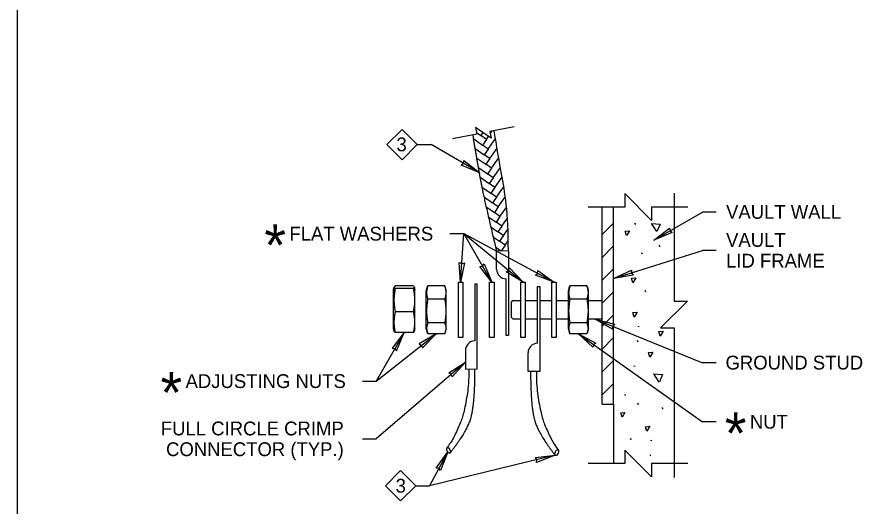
# Model space of a CAD drawing. Extents: x 99862 to 103151, y 100000 to 105076.
# Drawn here: x 99862 to 100847, y 103941 to 104508 of the extents above; entities that cross this region are included whole.
import ezdxf

# ---------------------------------------------------------------- set-up
doc = ezdxf.new("R2010")
doc.units = 0
for name, color, linetype in [('Level 1', 7, 'Continuous'), ('Level 10', 7, 'Continuous'), ('Level 11', 7, 'Continuous'), ('Level 13', 7, 'Continuous'), ('Level 15', 7, 'Continuous'), ('Level 20', 7, 'Continuous'), ('Level 30', 7, 'Continuous'), ('Level 8', 7, 'Continuous')]:
    doc.layers.add(name, color=color, linetype=linetype)

msp = doc.modelspace()

# ---------------------------------------------------------------- linework, layer by layer
at = {"layer": 'Level 1'}
for p, q in [((100539.11, 104060.59), (100539.11, 104288.59)), ((100552.29, 104060.59), (100552.29, 104288.59)), ((100552.29, 104270.05), (100539.11, 104256.87)), ((100552.29, 104243.53), (100539.11, 104230.35)), ((100552.29, 104217.01), (100539.11, 104203.84)), ((100552.29, 104190.5), (100539.11, 104177.32)), ((100552.29, 104163.98), (100539.11, 104150.8)), ((100552.29, 104137.47), (100539.11, 104124.29)), ((100552.29, 104110.95), (100539.11, 104097.77)), ((100552.29, 104084.43), (100539.11, 104071.25)), ((100539.11, 104060.59), (100552.29, 104060.59)), ((100552.29, 104060.59), (100552.29, 103991.68))]:
    msp.add_line(p, q, dxfattribs=at)
msp.add_lwpolyline([(99862, 102999.5), (103151, 102999.5), (103151, 105075.5), (99862, 105075.5)], close=True, dxfattribs=at)
at = {"layer": 'Level 10'}
for p, q in [((100297.82, 104193.2), (100298.6, 104196.01)), ((100299.66, 104197.24), (100298.6, 104196.01)), ((100320.67, 104197.24), (100299.66, 104197.24)), ((100320.67, 104197.24), (100321.73, 104196.01)), ((100321.73, 104196.01), (100322.52, 104193.19)), ((100335.58, 104191.07), (100337.09, 104196.48)), ((100337.09, 104196.46), (100337.31, 104197.24)), ((100357.01, 104197.24), (100337.31, 104197.24)), ((100357.24, 104196.46), (100357.01, 104197.24)), ((100357.23, 104196.48), (100358.74, 104191.07)), ((100500.06, 104191.07), (100501.56, 104196.48)), ((100501.56, 104196.46), (100501.79, 104197.24)), ((100521.48, 104197.24), (100501.79, 104197.24)), ((100521.71, 104196.46), (100521.48, 104197.24)), ((100521.7, 104196.48), (100523.21, 104191.07)), ((100320.67, 104194.25), (100299.66, 104194.25)), ((100335.58, 104148.22), (100335.58, 104191.07)), ((100358.74, 104148.22), (100358.74, 104191.07)), ((100500.06, 104148.22), (100500.06, 104191.07)), ((100523.21, 104148.22), (100523.21, 104191.07)), ((100357.01, 104182.09), (100337.31, 104182.09)), ((100436.13, 104180.58), (100433.88, 104178.33)), ((100433.88, 104178.33), (100433.88, 104160.96)), ((100436.13, 104180.58), (100444.98, 104180.58)), ((100450.25, 104180.58), (100464.39, 104180.58)), ((100467.03, 104180.58), (100480.84, 104180.58)), ((100486.11, 104180.58), (100500.06, 104180.58)), ((100521.48, 104182.09), (100501.79, 104182.09)), ((100523.21, 104180.58), (100539.11, 104180.58)), ((100320.67, 104167.35), (100299.66, 104167.35)), ((100433.88, 104160.96), (100436.13, 104158.71)), ((100444.98, 104158.71), (100436.13, 104158.71)), ((100464.39, 104158.71), (100450.25, 104158.71)), ((100480.84, 104158.71), (100467.03, 104158.71)), ((100500.06, 104158.71), (100486.11, 104158.71)), ((100539.11, 104158.71), (100523.21, 104158.71)), ((100298.6, 104144.68), (100297.82, 104147.49)), ((100322.51, 104147.49), (100321.73, 104144.68)), ((100337.3, 104142.05), (100335.58, 104148.22)), ((100357.01, 104154.5), (100337.31, 104154.5)), ((100358.74, 104148.22), (100357.23, 104142.81)), ((100501.78, 104142.05), (100500.06, 104148.22)), ((100521.48, 104154.5), (100501.79, 104154.5)), ((100523.21, 104148.22), (100521.7, 104142.81)), ((100299.66, 104143.45), (100298.6, 104144.68)), ((100320.67, 104143.45), (100299.66, 104143.45)), ((100320.67, 104143.45), (100321.73, 104144.68)), ((100357.01, 104142.05), (100337.31, 104142.05)), ((100357.24, 104142.83), (100357.01, 104142.05)), ((100521.48, 104142.05), (100501.79, 104142.05)), ((100521.71, 104142.83), (100521.48, 104142.05))]:
    msp.add_line(p, q, dxfattribs=at)
for centre, major_axis, start_param, end_param in [((100297.82, 104170.34), (0, 22.85), 5.657889, 6.283246), ((100297.82, 104170.34), (0, 22.85), 0.00006, 0.907855), ((100297.82, 104170.34), (0, 22.85), 3.141532, 5.657889), ((100322.51, 104170.34), (0, 22.85), 3.141653, 5.657889), ((100322.51, 104170.34), (0, 22.85), 5.657889, 6.283125), ((100297.82, 104170.34), (0, -14.06), 6.283185, 9.424778), ((100297.82, 104170.34), (0, 22.85), 2.233603, 3.141532), ((100297.82, 104170.34), (0, -14.06), 6.270079, 6.283185), ((100322.51, 104170.34), (0, -14.06), 6.270079, 6.283185)]:
    msp.add_ellipse(centre, major_axis=major_axis, ratio=0.000017, start_param=start_param, end_param=end_param, dxfattribs=at)
for points in [[(100298.6, 104196.01), (100298.37, 104195.42), (100299.02, 104194.83), (100299.66, 104194.25)], [(100321.73, 104196.01), (100321.96, 104195.42), (100321.32, 104194.83), (100320.67, 104194.25)], [(100337.31, 104197.24), (100336, 104192.22), (100335.85, 104187.11), (100337.31, 104182.09)], [(100357.01, 104197.24), (100358.32, 104192.22), (100358.47, 104187.11), (100357.01, 104182.09)], [(100501.79, 104197.24), (100500.48, 104192.22), (100500.33, 104187.11), (100501.79, 104182.09)], [(100521.48, 104197.24), (100522.79, 104192.22), (100522.94, 104187.11), (100521.48, 104182.09)], [(100299.66, 104194.25), (100298.15, 104185.28), (100298.19, 104176.32), (100299.66, 104167.35)], [(100320.67, 104194.25), (100322.18, 104185.28), (100322.14, 104176.32), (100320.67, 104167.35)], [(100337.31, 104182.09), (100335.9, 104172.89), (100335.93, 104163.7), (100337.31, 104154.5)], [(100357.01, 104182.09), (100358.42, 104172.89), (100358.39, 104163.7), (100357.01, 104154.5)], [(100501.79, 104182.09), (100500.37, 104172.89), (100500.41, 104163.7), (100501.79, 104154.5)], [(100521.48, 104182.09), (100522.9, 104172.89), (100522.86, 104163.7), (100521.48, 104154.5)], [(100299.66, 104167.35), (100298.26, 104159.43), (100298.1, 104151.37), (100299.66, 104143.45)], [(100320.67, 104167.35), (100322.07, 104159.43), (100322.23, 104151.37), (100320.67, 104143.45)], [(100337.31, 104154.5), (100336.08, 104150.61), (100335.85, 104146.72), (100337.09, 104142.83)], [(100357.01, 104154.5), (100358.24, 104150.61), (100358.48, 104146.72), (100357.24, 104142.83)], [(100501.79, 104154.5), (100500.55, 104150.61), (100500.32, 104146.72), (100501.56, 104142.83)], [(100521.48, 104154.5), (100522.72, 104150.61), (100522.95, 104146.72), (100521.71, 104142.83)]]:
    msp.add_open_spline(points, degree=2, dxfattribs=at)
at = {"layer": 'Level 11'}
for p, q in [((100393.61, 104375.03), (100398.68, 104371.48)), ((100401.09, 104374.93), (100398.68, 104371.48)), ((100409.72, 104373.3), (100412.05, 104376.62)), ((100390.5, 104367.44), (100400.64, 104360.34)), ((100405.23, 104366.89), (100398.68, 104371.48)), ((100405.23, 104366.89), (100400.64, 104360.34)), ((100405.23, 104366.89), (100407.72, 104370.45)), ((100407.2, 104355.75), (100415.7, 104367.89)), ((100392.33, 104356.39), (100402.61, 104349.2)), ((100407.2, 104355.75), (100400.64, 104360.34)), ((100407.2, 104355.75), (100402.61, 104349.2)), ((100409.16, 104344.61), (100417.6, 104356.66)), ((100394.28, 104345.26), (100404.57, 104338.05)), ((100409.16, 104344.61), (100402.61, 104349.2)), ((100409.16, 104344.61), (100404.57, 104338.05)), ((100411.12, 104333.47), (100419.53, 104345.47)), ((100396.36, 104334.04), (100399.98, 104331.5)), ((100411.12, 104333.47), (100404.57, 104338.05)), ((100411.12, 104333.47), (100406.54, 104326.91)), ((100411.12, 104333.47), (100411.12, 104333.47)), ((100413.09, 104322.33), (100421.43, 104334.23)), ((100398.59, 104322.71), (100408.5, 104315.77)), ((100399.98, 104331.5), (100406.54, 104326.91)), ((100413.09, 104322.32), (100406.54, 104326.91)), ((100415.05, 104311.18), (100423.26, 104322.91)), ((100413.09, 104322.32), (100408.5, 104315.77)), ((100415.05, 104311.18), (100408.5, 104315.77)), ((100400.85, 104311.36), (100410.47, 104304.63)), ((100415.05, 104311.18), (100410.47, 104304.63)), ((100417.02, 104300.04), (100410.47, 104304.63)), ((100417.02, 104300.04), (100424.99, 104311.43)), ((100403.18, 104299.96), (100412.43, 104293.49)), ((100417.02, 104300.04), (100412.43, 104293.49)), ((100418.98, 104288.9), (100412.43, 104293.49)), ((100418.98, 104288.9), (100426.57, 104299.73)), ((100405.68, 104288.45), (100414.4, 104282.35)), ((100418.98, 104288.9), (100414.4, 104282.35)), ((100420.95, 104277.76), (100427.94, 104287.75)), ((100408.18, 104276.93), (100416.36, 104271.2)), ((100420.95, 104277.76), (100414.4, 104282.35)), ((100420.95, 104277.76), (100416.36, 104271.2)), ((100422.91, 104266.62), (100429.08, 104275.43)), ((100410.8, 104265.33), (100418.32, 104260.06)), ((100422.91, 104266.62), (100416.36, 104271.2)), ((100422.91, 104266.62), (100418.32, 104260.06)), ((100413.52, 104253.66), (100420.29, 104248.92)), ((100424.88, 104255.47), (100418.32, 104260.06)), ((100424.88, 104255.47), (100420.29, 104248.92)), ((100424.88, 104255.48), (100429.95, 104262.71)), ((100426.84, 104244.33), (100420.29, 104248.92)), ((100426.84, 104244.33), (100422.61, 104238.29)), ((100426.84, 104244.33), (100430.49, 104249.54)), ((100416.23, 104242), (100421.49, 104238.31))]:
    msp.add_line(p, q, dxfattribs=at)
for points, degree in [([(100417.06, 104238.42), (100404.27, 104291.75), (100395.44, 104335.73), (100389.71, 104372.3)], 2), ([(100430.64, 104238.1), (100430.64, 104283.27), (100422.58, 104327.26), (100415.23, 104370.5), (100414.15, 104377.03)], 3)]:
    msp.add_open_spline(points, degree=degree, dxfattribs=at)
at = {"layer": 'Level 13'}
for p, q in [((100417.06, 104216.55), (100417.06, 104238.42)), ((100417.06, 104238.42), (100430.64, 104238.1)), ((100430.64, 104238.1), (100430.64, 104203.76)), ((100428, 104191.97), (100428, 104205.61)), ((100394.52, 104199.49), (100391.88, 104199.49)), ((100391.88, 104199.49), (100391.88, 104190.03)), ((100394.52, 104190.03), (100394.52, 104199.49)), ((100430.64, 104203.76), (100430.64, 104191.97)), ((100464.39, 104187.3), (100464.39, 104196.7)), ((100464.39, 104196.7), (100467.03, 104196.7)), ((100467.03, 104196.7), (100467.03, 104187.3)), ((100391.88, 104190.03), (100391.88, 104153.33)), ((100394.52, 104153.33), (100394.52, 104190.03)), ((100428, 104185.96), (100428, 104191.97)), ((100428, 104149.26), (100428, 104185.96)), ((100430.64, 104191.97), (100430.64, 104185.96)), ((100430.64, 104185.96), (100430.64, 104149.26)), ((100464.39, 104150.6), (100464.39, 104187.3)), ((100467.03, 104187.3), (100467.03, 104150.6)), ((100391.88, 104153.33), (100391.88, 104147.32)), ((100391.88, 104147.32), (100391.88, 104133.68)), ((100394.52, 104147.32), (100394.52, 104153.33)), ((100394.52, 104135.53), (100394.52, 104147.32)), ((100428, 104139.8), (100428, 104149.26)), ((100430.64, 104149.26), (100430.64, 104139.8)), ((100464.39, 104144.57), (100464.39, 104150.6)), ((100467.03, 104150.6), (100467.03, 104144.57)), ((100394.52, 104101.19), (100394.52, 104135.53)), ((100430.64, 104139.8), (100428, 104139.8)), ((100464.39, 104130.89), (100464.39, 104144.57)), ((100467.03, 104144.57), (100467.03, 104132.77)), ((100467.03, 104132.77), (100467.03, 104098.44)), ((100380.94, 104122.74), (100380.94, 104100.87)), ((100453.45, 104098.44), (100453.45, 104119.95)), ((100380.94, 104100.87), (100394.52, 104101.19)), ((100467.03, 104098.44), (100453.45, 104098.44))]:
    msp.add_line(p, q, dxfattribs=at)
for points in [[(100378.01, 104137.78), (100372.74, 104137.78), (100372.74, 104201.51), (100378.01, 104201.51)], [(100414.13, 104137.78), (100408.86, 104137.78), (100408.86, 104201.51), (100414.13, 104201.51)], [(100450.25, 104137.78), (100444.98, 104137.78), (100444.98, 104201.51), (100450.25, 104201.51)], [(100486.11, 104137.78), (100480.84, 104137.78), (100480.84, 104201.51), (100486.11, 104201.51)]]:
    msp.add_lwpolyline(points, close=True, dxfattribs=at)
for centre, start, end in [((100428, 104216.55), 180, 270), ((100391.88, 104122.74), 90, 180), ((100464.39, 104119.95), 90, 180)]:
    msp.add_arc(centre, 10.94, start, end, dxfattribs=at)
at = {"layer": 'Level 15'}
for p, q in [((100325.14, 104360.83), (100341.14, 104360.83)), ((100397.43, 104328.33), (100341.14, 104360.83)), ((100598.89, 104250.23), (100655.18, 104282.73)), ((100671.18, 104282.73), (100655.18, 104282.73)), ((100363, 104257.8), (100379, 104257.8)), ((100375.38, 104201.51), (100379, 104257.8)), ((100411.5, 104201.51), (100379, 104257.8)), ((100379, 104257.8), (100483.48, 104201.51)), ((100379, 104257.8), (100447.62, 104201.51)), ((100552.29, 104205.76), (100655.18, 104238.26)), ((100671.18, 104238.26), (100655.18, 104238.26)), ((100531.16, 104158.71), (100655.18, 104108.3)), ((100310.17, 104143.45), (100277.67, 104087.16)), ((100277.67, 104087.16), (100347.16, 104142.05)), ((100511.63, 104142.05), (100655.18, 104039.86)), ((100380.94, 104109.19), (100277.67, 104020.34)), ((100671.18, 104108.3), (100655.18, 104108.3)), ((100261.67, 104087.16), (100277.67, 104087.16)), ((100671.18, 104039.86), (100655.18, 104039.86)), ((100261.67, 104020.34), (100277.67, 104020.34)), ((100360.4, 104005.2), (100339.5, 103966.08)), ((100484.81, 104001.37), (100339.5, 103966.08)), ((100323.5, 103966.08), (100339.5, 103966.08))]:
    msp.add_line(p, q, dxfattribs=at)
for points in [[(100437.19, 104381.49), (100409.18, 104376.07), (100410.65, 104368.47), (100392.5, 104380.73), (100393.98, 104373.12), (100365.96, 104367.7)], [(100638.35, 104288.59), (100596.22, 104288.59), (100596.22, 104273.11), (100565.24, 104304.08), (100565.24, 104288.59), (100523.11, 104288.59)], [(100622.35, 104304.59), (100622.35, 104179.63), (100637.84, 104179.63), (100606.86, 104148.66), (100622.35, 104148.66), (100622.35, 103975.68)], [(100638.35, 103991.68), (100596.22, 103991.68), (100596.22, 103976.2), (100565.24, 104007.17), (100565.24, 103991.68), (100523.11, 103991.68)]]:
    msp.add_lwpolyline(points, dxfattribs=at)
for points in [[(100397.43, 104328.33), (100376.17, 104337.16), (100378.58, 104339.22), (100379.16, 104342.34)], [(100598.89, 104250.23), (100617.17, 104264.22), (100617.74, 104261.11), (100620.15, 104259.06)], [(100375.38, 104201.51), (100373.86, 104224.48), (100376.77, 104223.24), (100379.82, 104224.1)], [(100411.5, 104201.51), (100397.5, 104219.79), (100400.61, 104220.36), (100402.67, 104222.77)], [(100447.62, 104201.51), (100428.07, 104213.68), (100430.78, 104215.32), (100431.86, 104218.3)], [(100483.48, 104201.51), (100461.96, 104209.71), (100464.31, 104211.84), (100464.79, 104214.97)], [(100552.29, 104205.76), (100573.16, 104215.48), (100573.05, 104212.32), (100574.96, 104209.79)], [(100531.16, 104158.71), (100553.43, 104152.88), (100551.33, 104150.51), (100551.19, 104147.35)], [(100310.17, 104143.45), (100296.17, 104125.17), (100299.28, 104124.59), (100301.34, 104122.18)], [(100347.16, 104142.05), (100327.4, 104130.24), (100330.08, 104128.55), (100331.1, 104125.56)], [(100511.63, 104142.05), (100531.96, 104131.24), (100529.37, 104129.42), (100528.5, 104126.38)], [(100380.94, 104109.19), (100365.58, 104092.04), (100364.44, 104094.99), (100361.69, 104096.57)], [(100360.4, 104005.2), (100352.28, 103983.66), (100350.14, 103986), (100347.01, 103986.48)], [(100484.81, 104001.37), (100463.33, 103993.08), (100463.65, 103996.23), (100461.92, 103998.88)]]:
    msp.add_lwpolyline(points, close=True, dxfattribs=at)
at = {"layer": 'Level 20'}
for points in [[(100307.59, 104343.28), (100290.04, 104360.83), (100307.59, 104378.39), (100325.14, 104360.83)], [(100305.94, 103983.64), (100323.5, 103966.08), (100305.94, 103948.53), (100288.39, 103966.08)]]:
    msp.add_lwpolyline(points, close=True, dxfattribs=at)
at = {"layer": 'Level 30'}
for centre, major_axis in [((100361.37, 104007.02), (1.43, -3.35)), ((100486.59, 104004.43), (-1.43, -3.35))]:
    msp.add_ellipse(centre, major_axis=major_axis, ratio=0.472935, dxfattribs=at)
for points, degree in [([(100384.85, 104101.03), (100384.85, 104086.56), (100383.63, 104073.7), (100379.23, 104050.77), (100376.04, 104040.7), (100368.5, 104023.65), (100364.28, 104016.47), (100359.55, 104010.04)], 3), ([(100391.6, 104101.03), (100391.6, 104056.46), (100380.35, 104026.01), (100363.16, 104003.96)], 2), ([(100456.37, 104098.44), (100456.37, 104053.87), (100467.62, 104023.41), (100484.81, 104001.37)], 2), ([(100463.12, 104098.44), (100463.12, 104083.96), (100464.34, 104071.1), (100468.74, 104048.18), (100471.92, 104038.11), (100479.47, 104021.06), (100483.69, 104013.88), (100488.42, 104007.44)], 3)]:
    msp.add_open_spline(points, degree=degree, dxfattribs=at)
at = {"layer": 'Level 8'}
for p, q in [((100576.77, 104269.92), (100578.1, 104268.74)), ((100605.95, 104242.53), (100605.39, 104244.37)), ((100584.36, 104235.39), (100585.73, 104235.04)), ((100589.6, 104190.16), (100589.01, 104191.99)), ((100580.53, 104150.89), (100581.89, 104150.54)), ((100580.77, 104132.22), (100580.17, 104134.05)), ((100575.88, 104104.95), (100577.25, 104104.6)), ((100581.12, 104059.72), (100580.52, 104061.55)), ((100609.5, 104054.77), (100608.9, 104056.6)), ((100571.17, 104020.26), (100572.46, 104019.93)), ((100572.04, 104020.45), (100572.96, 104020.22)), ((100595.23, 104018.83), (100596.59, 104018.48)), ((100595.47, 104000.16), (100594.87, 104001.99))]:
    msp.add_line(p, q, dxfattribs=at)
for points in [[(100602.53, 104260.12), (100596.21, 104269.45), (100606.25, 104268.76), (100602.63, 104260.29)], [(100567.32, 104255.47), (100565.79, 104260.67), (100570.66, 104261.11), (100567.32, 104255.47)], [(100574.63, 104201), (100573.11, 104206.2), (100577.97, 104206.64), (100574.63, 104201)], [(100576.19, 104161.26), (100574.66, 104166.46), (100579.53, 104166.89), (100576.19, 104161.26)], [(100606.37, 104139.24), (100604.84, 104144.44), (100609.71, 104144.88), (100606.37, 104139.24)], [(100594.53, 104114.9), (100593, 104120.1), (100597.86, 104120.54), (100594.53, 104114.9)], [(100605.32, 104086.11), (100599, 104095.45), (100609.04, 104094.76), (100605.41, 104086.28)], [(100566.15, 104070.56), (100565.73, 104072.01)], [(100562.27, 104045.27), (100560.75, 104050.47), (100565.61, 104050.9), (100562.27, 104045.27)], [(100590.89, 104029.2), (100589.36, 104034.39), (100594.23, 104034.83), (100590.89, 104029.2)]]:
    msp.add_lwpolyline(points, dxfattribs=at)

# ---------------------------------------------------------------- texts
at = {"layer": 'Level 20'}
for s, height, p in [('3', 16, (100301.14, 104353.1)), ('VAULT WALL', 16, (100682.58, 104274.99)), ('*', 48, (100148.25, 104220.53)), ('FLAT WASHERS', 16, (100177.25, 104249.8)), ('VAULT ', 16, (100682.58, 104242.52)), ('LID FRAME', 16, (100682.58, 104218.52)), ('GROUND STUD', 16, (100681.95, 104100.56)), ('*', 48, (100028.07, 104049.88)), ('ADJUSTING NUTS', 16, (100057.08, 104079.16)), ('*', 48, (100681.17, 104002.85)), ('NUT', 16, (100710.18, 104032.12)), ('FULL CIRCLE CRIMP ', 16, (100028.44, 104024.34)), ('CONNECTOR (TYP.)', 16, (100034.5, 104000.34)), ('3', 16, (100300.16, 103958.08))]:
    msp.add_text(s, height=height, dxfattribs=at).set_placement(p)

doc.saveas('drawing.dxf')
